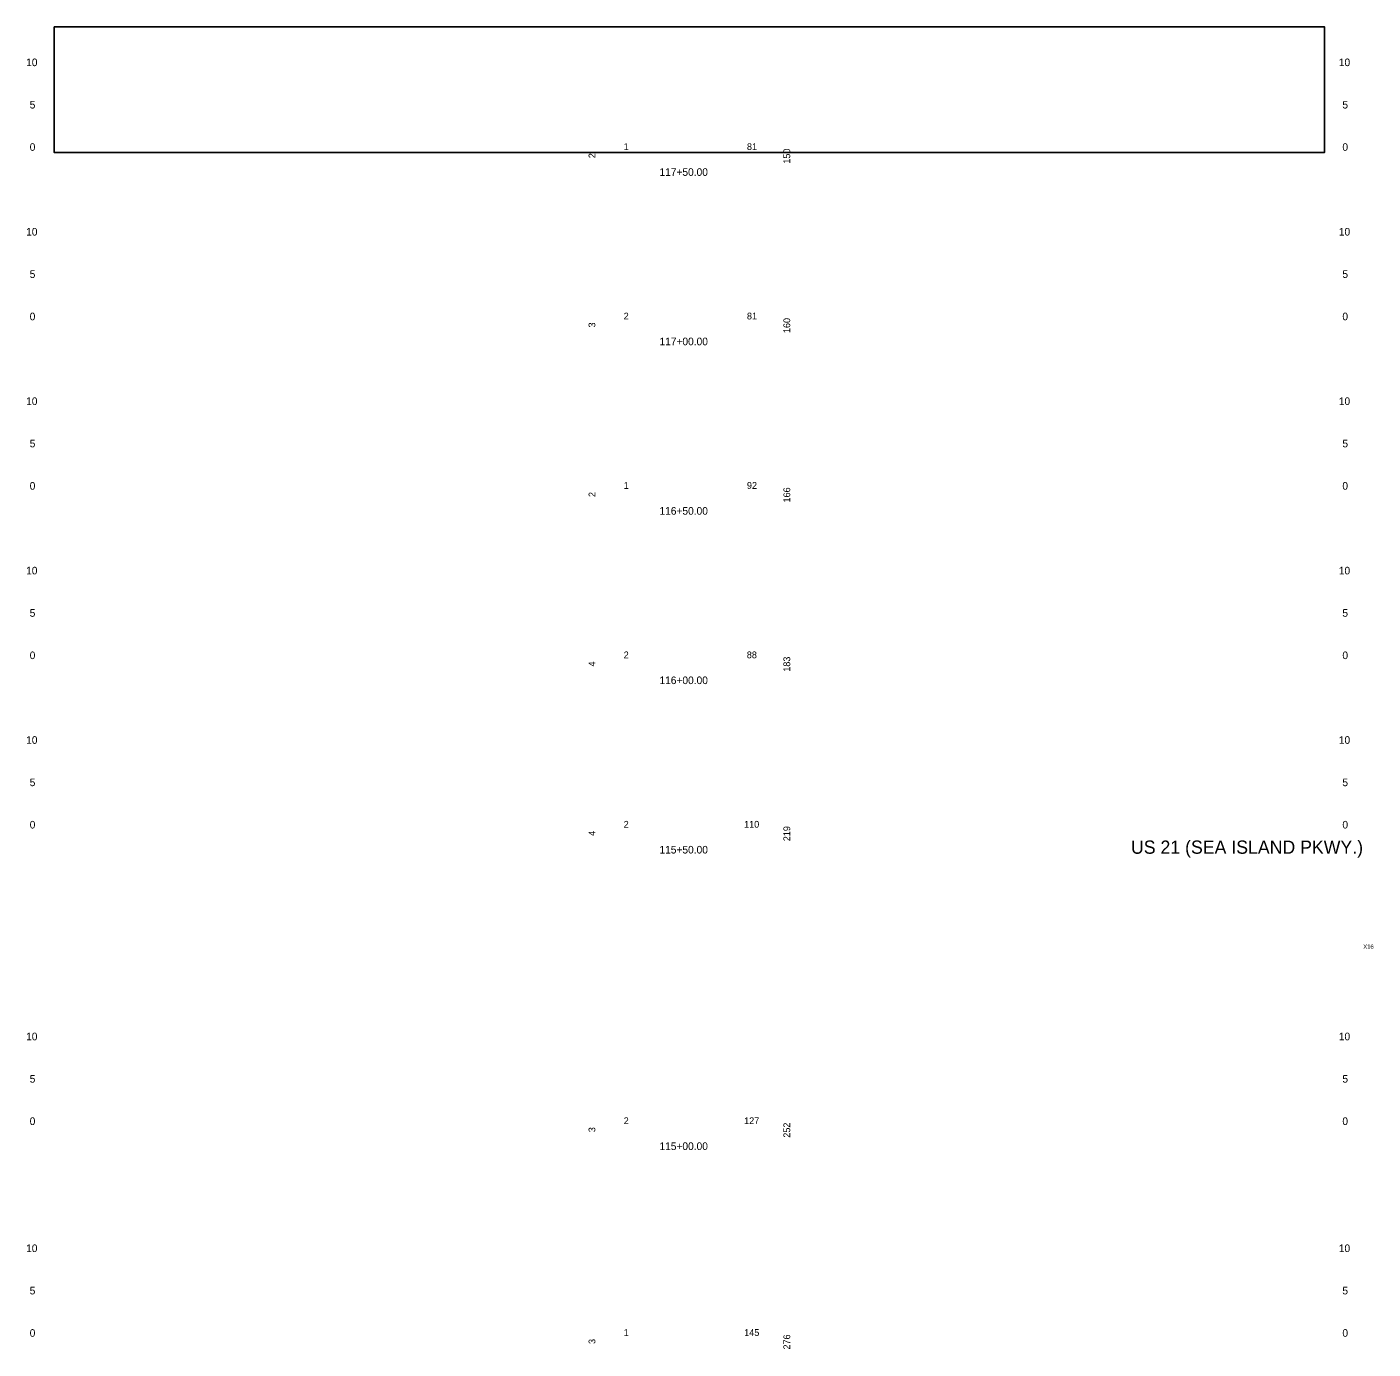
# Model space of a CAD drawing. Extents: x 971 to 1131, y 2203 to 6043.
# Drawn here: x 971.5 to 1130.5, y 5445.4 to 5601.5 of the extents above; entities that cross this region are included whole.
import ezdxf

# ---------------------------------------------------------------- set-up
doc = ezdxf.new("R2010")
doc.units = 0
for name, color, linetype in [('RD_SHT_Misc1', 7, 'Continuous'), ('RD_SHT_ShtClip', 7, 'Continuous'), ('RD_SHT_TX', 7, 'Continuous'), ('RD_XS_TX_Station', 7, 'Continuous')]:
    doc.layers.add(name, color=color, linetype=linetype)

msp = doc.modelspace()

# ---------------------------------------------------------------- linework, layer by layer
at = {"layer": 'RD_SHT_ShtClip'}
msp.add_lwpolyline([(974.73, 5601.5), (1124.73, 5601.5), (1124.73, 5586.68), (974.73, 5586.68)], close=True, dxfattribs=at)

# ---------------------------------------------------------------- texts
at = {"layer": 'RD_SHT_Misc1'}
for s, p in [('1', (1041.98, 5586.97)), ('81', (1056.53, 5586.97)), ('2', (1041.98, 5566.97)), ('81', (1056.53, 5566.97)), ('1', (1041.98, 5546.97)), ('92', (1056.53, 5546.97)), ('2', (1041.98, 5526.97)), ('88', (1056.52, 5526.97)), ('2', (1041.98, 5506.97)), ('110', (1056.2, 5506.97)), ('2', (1041.98, 5471.97)), ('127', (1056.2, 5471.97)), ('1', (1041.98, 5446.97)), ('145', (1056.21, 5446.97))]:
    msp.add_text(s, height=0.8, dxfattribs=at).set_placement(p)
for s, p in [('2', (1038.63, 5586.01)), ('150', (1061.64, 5585.36)), ('3', (1038.63, 5566.02)), ('160', (1061.64, 5565.36)), ('2', (1038.63, 5546.01)), ('166', (1061.64, 5545.36)), ('183', (1061.64, 5525.38)), ('4', (1038.63, 5526)), ('4', (1038.63, 5506)), ('219', (1061.64, 5505.37)), ('3', (1038.63, 5471.02)), ('252', (1061.64, 5470.37)), ('3', (1038.63, 5446.02)), ('276', (1061.64, 5445.36))]:
    msp.add_text(s, height=0.8, rotation=90, dxfattribs=at).set_placement(p)
at = {"layer": 'RD_SHT_TX'}
for s, height, p in [('10', 0.9, (971.42, 5596.87)), ('10', 0.9, (1126.42, 5596.87)), ('5', 0.9, (971.84, 5591.87)), ('5', 0.9, (1126.84, 5591.87)), ('0', 0.9, (971.84, 5586.87)), ('0', 0.9, (1126.84, 5586.87)), ('10', 0.9, (971.42, 5576.87)), ('10', 0.9, (1126.42, 5576.87)), ('5', 0.9, (971.84, 5571.87)), ('5', 0.9, (1126.84, 5571.87)), ('0', 0.9, (971.84, 5566.87)), ('0', 0.9, (1126.84, 5566.87)), ('10', 0.9, (971.42, 5556.87)), ('10', 0.9, (1126.42, 5556.87)), ('5', 0.9, (971.84, 5551.87)), ('5', 0.9, (1126.84, 5551.87)), ('0', 0.9, (971.84, 5546.87)), ('0', 0.9, (1126.84, 5546.87)), ('10', 0.9, (971.42, 5536.87)), ('10', 0.9, (1126.42, 5536.87)), ('5', 0.9, (971.84, 5531.87)), ('5', 0.9, (1126.84, 5531.87)), ('0', 0.9, (971.84, 5526.87)), ('0', 0.9, (1126.84, 5526.87)), ('10', 0.9, (971.42, 5516.87)), ('10', 0.9, (1126.42, 5516.87)), ('5', 0.9, (971.84, 5511.87)), ('5', 0.9, (1126.84, 5511.87)), ('0', 0.9, (971.84, 5506.87)), ('0', 0.9, (1126.84, 5506.87)), ('US 21 (SEA ISLAND PKWY.)', 1.5625, (1101.88, 5503.89)), ('10', 0.9, (971.42, 5481.87)), ('10', 0.9, (1126.42, 5481.87)), ('5', 0.9, (971.84, 5476.87)), ('5', 0.9, (1126.84, 5476.87)), ('0', 0.9, (971.84, 5471.87)), ('0', 0.9, (1126.84, 5471.87)), ('10', 0.9, (971.42, 5456.87)), ('10', 0.9, (1126.42, 5456.87)), ('5', 0.9, (971.84, 5451.87)), ('5', 0.9, (1126.84, 5451.87)), ('0', 0.9, (971.84, 5446.87)), ('0', 0.9, (1126.84, 5446.87))]:
    msp.add_text(s, height=height, dxfattribs=at).set_placement(p)
msp.add_text('X16', height=0.5, rotation=360, dxfattribs=at).set_placement((1129.31, 5492.68))
at = {"layer": 'RD_XS_TX_Station'}
for s, p in [('117+50.00', (1046.2, 5583.92)), ('117+00.00', (1046.2, 5563.92)), ('116+50.00', (1046.2, 5543.92)), ('116+00.00', (1046.2, 5523.92)), ('115+50.00', (1046.2, 5503.92)), ('115+00.00', (1046.2, 5468.92))]:
    msp.add_text(s, height=0.9, dxfattribs=at).set_placement(p)

doc.saveas('drawing.dxf')
